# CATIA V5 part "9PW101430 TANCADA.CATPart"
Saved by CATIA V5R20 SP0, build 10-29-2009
Part number: 9PW101430 TANCADA
Revision: ANY
Definition: UNKNOWN
Nomenclature: 9PW101430 TANCADA
Source: Unknown
Bounding box of the stored display mesh (mm): x -175 to 0, y -8.113 to 5.5, z -7.1 to 7.1
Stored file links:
  C:\Users\Utente\Desktop\IO LAVORO\3D X SITO CF\CUMSA\3D files PW\pw101430\pw101430_injection\9PW101430 TANCADA.CATPart
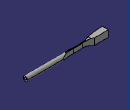
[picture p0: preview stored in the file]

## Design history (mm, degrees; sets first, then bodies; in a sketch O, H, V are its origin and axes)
Body1 "Chaflán5" (main body)
  Solid1: solid without history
